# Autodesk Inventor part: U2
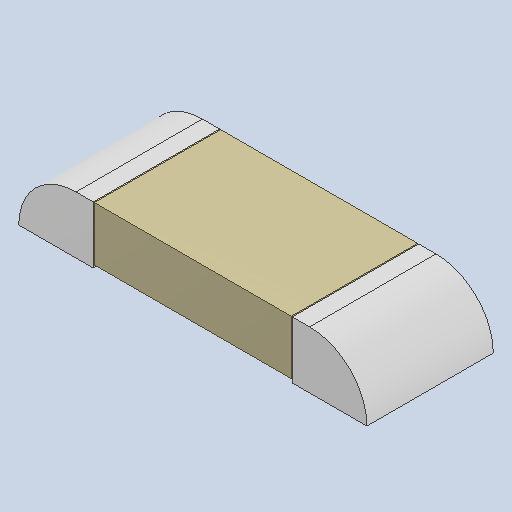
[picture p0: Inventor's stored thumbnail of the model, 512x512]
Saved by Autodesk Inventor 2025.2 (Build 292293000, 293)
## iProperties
Created: 2025-04
Part Number: U2
Material: Generic
Description: PART-U2-DESC
Document SubType Name: Modeling
Designer: BennF
Density: 1 g/cm^3
Appearance: Default
Author: BennF
Revision Number: NONE
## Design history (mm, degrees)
feature "pin"
feature "Solid"
body "Solid1"
body "Solid2"
